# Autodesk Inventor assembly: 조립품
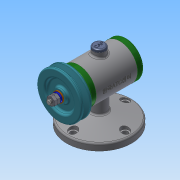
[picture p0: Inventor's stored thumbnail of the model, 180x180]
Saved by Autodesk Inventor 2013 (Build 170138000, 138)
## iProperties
Created: 2018-12
Part Number: 조립품
Document SubType Name: Assembly
Designer: Administrator
Author: Administrator
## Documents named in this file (15)
- C:\Users\Administrator\Desktop\481207V1035\조립품.iam
- C:\Users\Administrator\Desktop\481207V1035\본체.ipt
- C:\Users\Administrator\Desktop\481207V1035\베어링 15 x 32 x 9.ipt
- C:\Users\Administrator\Desktop\481207V1035\뒤커버.ipt
- C:\Users\Administrator\Desktop\481207V1035\볼트 M4 x 12.ipt
- C:\Users\Administrator\Desktop\481207V1035\축.ipt
- C:\Users\Administrator\Desktop\481207V1035\키 3 x 3 x 12.ipt
- C:\Users\Administrator\Desktop\481207V1035\앞커버.ipt
- C:\Users\Administrator\Desktop\481207V1035\V벨트풀리.ipt
- C:\Users\Administrator\Desktop\481207V1035\스프링와셔 8.ipt
- C:\Users\Administrator\Desktop\481207V1035\와셔 8x17.ipt
- C:\Users\Administrator\Desktop\481207V1035\너트 M8.ipt
- 너트 M8.ipt
- C:\Users\Administrator\Desktop\481207V1035\고무캡.ipt
- C:\Users\Administrator\Desktop\481207V1035\오일 실 15 25 7.ipt
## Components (2 placed, 2 different names)
1. V벨트풀리:1
2. 고무캡:1
